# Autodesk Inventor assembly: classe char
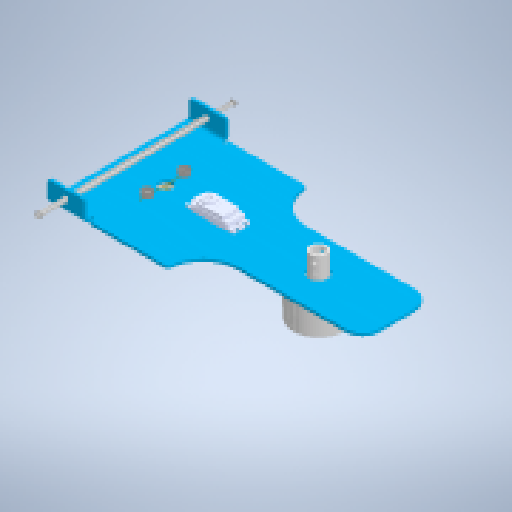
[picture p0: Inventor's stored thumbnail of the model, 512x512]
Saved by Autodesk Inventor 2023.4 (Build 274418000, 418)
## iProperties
Created: 2023-11
Part Number: classe char
Document SubType Name: Assembly
Designer: mel
Author: mel
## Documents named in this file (10)
- D:\travail\année 2023-2024\IT\char à voile\classe char.iam
- D:\travail\année 2023-2024\IT\char à voile\axe roues arrières.ipt
- D:\travail\année 2023-2024\IT\char à voile\char.ipt
- C:\Users\mel\Documents\Inventor\Content Center Files\R2023\fr-FR\NF L 23-203\NF L 23-203 - 2,3 - 3.ipt
- D:\travail\année 2023-2024\IT\char à voile\142231525-9-skf_bearing_w_618_8_2\skf_bearing_w_618_8_2.iam
- C:\Users\mel\Documents\Inventor\Content Center Files\R2023\fr-FR\NF E 22-165\NF E 22-165 - 16x1.ipt
- D:\travail\année 2023-2024\IT\char à voile\boitard roulement mat.ipt
- C:\Users\mel\Documents\Inventor\Content Center Files\R2023\fr-FR\ISO 4762(2)\ISO 4762 - M6 x 10ISO.ipt
- D:\travail\année 2023-2024\IT\char à voile\hitec-hs-485hb-1.snapshot.2\SERVO\SERVOMOTORE Hitec HS485-HB.ipt
- D:\travail\année 2023-2024\IT\char à voile\girouette partie fixe.iam
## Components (12 placed, 9 different names)
1. axe roues arrières:1 — Placage:1, Affleurement:1, Logement:1, Logement:2
2. char:1 — Placage:1, Affleurement:1, Logement:3, Angle:1, Logement:5, Logement:6, Placage:10, Affleurement:2, Affleurement:3, Placage:11, Placage:12
3. NF L 23-203 2,3:1 — Logement:2
4. NF L 23-203 2,3:2 — Logement:1
5. skf_bearing_w_618_8_2:1 [sub-assembly] — Placage:6, Placage:7, Placage:8
6. skf_bearing_w_618_8_2:2 [sub-assembly] — Logement:3, Placage:6, Placage:7, Logement:4
7. NF E 22-165 16x1:1 — Placage:8, Placage:9
8. boitard roulement mat:1 — Logement:4, Angle:1, Placage:9
9. ISO 4762 M6 x 10:1 — Logement:5
10. ISO 4762 M6 x 10:2 — Logement:6
11. SERVOMOTORE Hitec HS485-HB:1 — Placage:10, Affleurement:2, Affleurement:3
12. girouette partie fixe:1 [sub-assembly] — Placage:11, Placage:12
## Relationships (18: Mate 8, Insert 6, Flush 3, Angle 1)
- Placage:1 [Mate]: axe roues arrières:1 ↔ char:1
- Affleurement:1 [Flush]: axe roues arrières:1 ↔ char:1
- Logement:1 [Insert]: axe roues arrières:1 ↔ NF L 23-203 2,3:2
- Logement:2 [Insert]: axe roues arrières:1 ↔ NF L 23-203 2,3:1
- Logement:3 [Insert]: char:1 ↔ skf_bearing_w_618_8_2:2
- Placage:6 [Mate]: skf_bearing_w_618_8_2:1 ↔ skf_bearing_w_618_8_2:2
- Placage:7 [Mate]: skf_bearing_w_618_8_2:1 ↔ skf_bearing_w_618_8_2:2
- Logement:4 [Insert]: skf_bearing_w_618_8_2:2 ↔ boitard roulement mat:1
- Angle:1: char:1 ↔ boitard roulement mat:1
- Logement:5 [Insert]: char:1 ↔ ISO 4762 M6 x 10:1
- Logement:6 [Insert]: char:1 ↔ ISO 4762 M6 x 10:2
- Placage:8 [Mate]: skf_bearing_w_618_8_2:1 ↔ NF E 22-165 16x1:1
- Placage:9 [Mate]: NF E 22-165 16x1:1 ↔ boitard roulement mat:1
- Placage:10 [Mate]: char:1 ↔ SERVOMOTORE Hitec HS485-HB:1
- Affleurement:2 [Flush]: char:1 ↔ SERVOMOTORE Hitec HS485-HB:1
- Affleurement:3 [Flush]: char:1 ↔ SERVOMOTORE Hitec HS485-HB:1
- Placage:11 [Mate]: char:1 ↔ girouette partie fixe:1
- Placage:12 [Mate]: char:1 ↔ girouette partie fixe:1
